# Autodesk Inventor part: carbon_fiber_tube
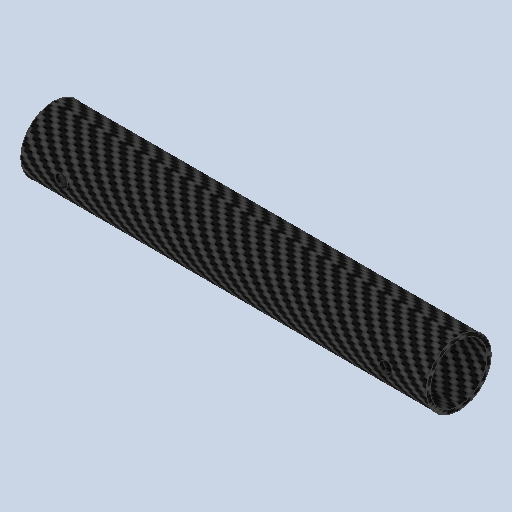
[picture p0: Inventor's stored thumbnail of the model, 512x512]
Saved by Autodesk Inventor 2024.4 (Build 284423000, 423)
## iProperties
Created: 2026-01
Part Number: carbon_fiber_tube
Material: Generic
Document SubType Name: Modeling
Designer: AdminForWorker
Density: 1 g/cm^3
Appearance: Default
Title: carbon_fiber_tube
Author: AdminForWorker
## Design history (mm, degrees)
feature "Body1"
body "Solid1"
